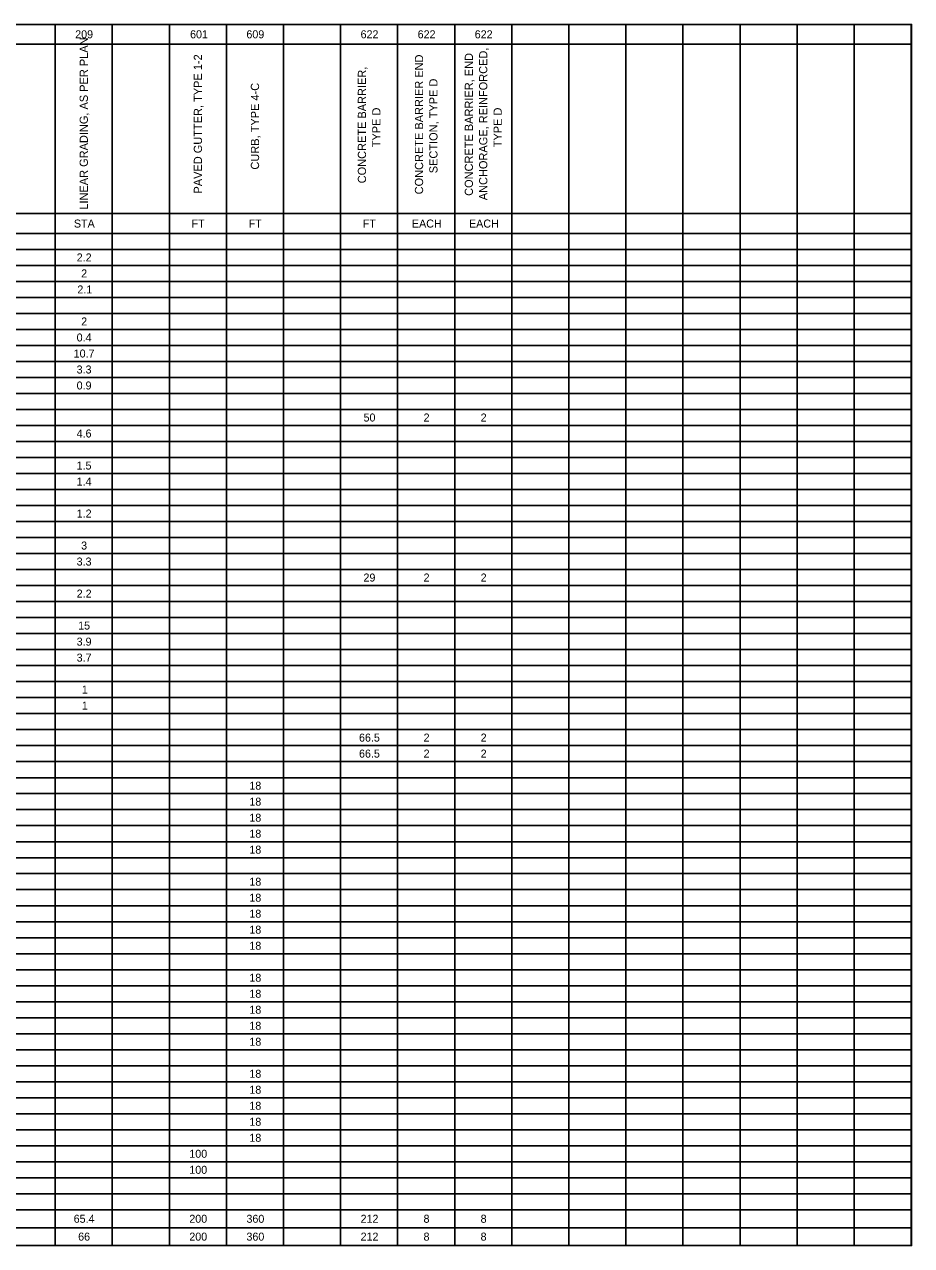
# Model space of a CAD drawing. Extents: x -542 to 295, y -281 to 32.
# Drawn here: x -1.11 to 14.14, y -130.59 to -109.59 of the extents above; entities that cross this region are included whole.
import ezdxf

# ---------------------------------------------------------------- set-up
doc = ezdxf.new("R2010")
doc.units = 0
doc.layers.add('SC_Scratch1', color=7, linetype='Continuous')
doc.layers.add('SH_Text', color=7, linetype='Continuous')

msp = doc.modelspace()

# ---------------------------------------------------------------- linework, layer by layer
at = {"layer": 'SC_Scratch1'}
msp.add_lwpolyline([(-16.359, -109.593), (14.141, -109.593), (14.141, -130.593), (-16.359, -130.593)], close=True, dxfattribs=at)
at = {"layer": 'SH_Text'}
for p, q in [((-16.359, -109.593), (14.136, -109.593)), ((-0.579, -109.593), (-0.579, -130.594)), ((0.402, -109.593), (0.402, -130.594)), ((1.383, -109.593), (1.383, -130.594)), ((2.364, -109.593), (2.364, -130.594)), ((3.345, -109.593), (3.345, -130.594)), ((4.326, -109.593), (4.326, -130.594)), ((5.307, -109.593), (5.307, -130.594)), ((6.288, -109.593), (6.288, -130.594)), ((7.269, -109.593), (7.269, -130.594)), ((8.25, -109.593), (8.25, -130.594)), ((9.231, -109.593), (9.231, -130.594)), ((10.212, -109.593), (10.212, -130.594)), ((11.193, -109.593), (11.193, -130.594)), ((12.174, -109.593), (12.174, -130.594)), ((13.155, -109.593), (13.155, -130.594)), ((14.136, -109.593), (14.136, -130.594)), ((-9.408, -109.933), (14.136, -109.933)), ((-9.408, -112.847), (14.136, -112.847)), ((-16.359, -113.187), (14.136, -113.187)), ((-16.359, -113.463), (14.136, -113.463)), ((-16.359, -113.738), (14.136, -113.738)), ((-16.359, -114.013), (14.136, -114.013)), ((-16.359, -114.288), (14.136, -114.288)), ((-16.359, -114.564), (14.136, -114.564)), ((-16.359, -114.839), (14.136, -114.839)), ((-16.359, -115.114), (14.136, -115.114)), ((-16.359, -115.389), (14.136, -115.389)), ((-16.359, -115.665), (14.136, -115.665)), ((-16.359, -115.94), (14.136, -115.94)), ((-16.359, -116.215), (14.136, -116.215)), ((-16.359, -116.491), (14.136, -116.491)), ((-16.359, -116.766), (14.136, -116.766)), ((-16.359, -117.041), (14.136, -117.041)), ((-16.359, -117.316), (14.136, -117.316)), ((-16.359, -117.592), (14.136, -117.592)), ((-16.359, -117.867), (14.136, -117.867)), ((-16.359, -118.142), (14.136, -118.142)), ((-16.359, -118.417), (14.136, -118.417)), ((-16.359, -118.693), (14.136, -118.693)), ((-16.359, -118.968), (14.136, -118.968)), ((-16.359, -119.243), (14.136, -119.243)), ((-16.359, -119.519), (14.136, -119.519)), ((-16.359, -119.794), (14.136, -119.794)), ((-16.359, -120.069), (14.136, -120.069)), ((-16.359, -120.344), (14.136, -120.344)), ((-16.359, -120.62), (14.136, -120.62)), ((-16.359, -120.895), (14.136, -120.895)), ((-16.359, -121.17), (14.136, -121.17)), ((-16.359, -121.445), (14.136, -121.445)), ((-16.359, -121.721), (14.136, -121.721)), ((-16.359, -121.996), (14.136, -121.996)), ((-16.359, -122.271), (14.136, -122.271)), ((-16.359, -122.547), (14.136, -122.547)), ((-16.359, -122.822), (14.136, -122.822)), ((-16.359, -123.097), (14.136, -123.097)), ((-16.359, -123.372), (14.136, -123.372)), ((-16.359, -123.648), (14.136, -123.648)), ((-16.359, -123.923), (14.136, -123.923)), ((-16.359, -124.198), (14.136, -124.198)), ((-16.359, -124.473), (14.136, -124.473)), ((-16.359, -124.749), (14.136, -124.749)), ((-16.359, -125.024), (14.136, -125.024)), ((-16.359, -125.299), (14.136, -125.299)), ((-16.359, -125.575), (14.136, -125.575)), ((-16.359, -125.85), (14.136, -125.85)), ((-16.359, -126.125), (14.136, -126.125)), ((-16.359, -126.4), (14.136, -126.4)), ((-16.359, -126.676), (14.136, -126.676)), ((-16.359, -126.951), (14.136, -126.951)), ((-16.359, -127.226), (14.136, -127.226)), ((-16.359, -127.501), (14.136, -127.501)), ((-16.359, -127.777), (14.136, -127.777)), ((-16.359, -128.052), (14.136, -128.052)), ((-16.359, -128.327), (14.136, -128.327)), ((-16.359, -128.603), (14.136, -128.603)), ((-16.359, -128.878), (14.136, -128.878)), ((-16.359, -129.153), (14.136, -129.153)), ((-16.359, -129.428), (14.136, -129.428)), ((-16.359, -129.704), (14.136, -129.704)), ((-16.359, -129.979), (14.136, -129.979)), ((-16.359, -130.287), (14.136, -130.287)), ((-16.359, -130.594), (14.136, -130.594))]:
    msp.add_line(p, q, dxfattribs=at)

# ---------------------------------------------------------------- texts
for s, height, p in [('209', 0.1376, (-0.236, -109.831)), ('601', 0.1376, (1.739, -109.831)), ('609', 0.1376, (2.707, -109.831)), ('622', 0.1376, (4.67, -109.831)), ('622', 0.1376, (5.651, -109.831)), ('622', 0.1376, (6.632, -109.831)), ('STA', 0.1376, (-0.258, -113.086)), ('FT', 0.1376, (1.765, -113.086)), ('FT', 0.1376, (2.746, -113.086)), ('FT', 0.1376, (4.708, -113.086)), ('EACH', 0.1376, (5.553, -113.086)), ('EACH', 0.1376, (6.534, -113.086)), ('2.2', 0.1376, (-0.21, -113.669)), ('2', 0.138, (-0.133, -113.944)), ('2.1', 0.1376, (-0.199, -114.22)), ('2', 0.138, (-0.133, -114.77)), ('0.4', 0.1376, (-0.211, -115.045)), ('10.7', 0.1376, (-0.262, -115.321)), ('3.3', 0.1376, (-0.211, -115.596)), ('0.9', 0.1376, (-0.211, -115.871)), ('50', 0.1376, (4.721, -116.422)), ('2', 0.138, (5.753, -116.422)), ('2', 0.138, (6.734, -116.422)), ('4.6', 0.1376, (-0.211, -116.697)), ('1.5', 0.1376, (-0.212, -117.248)), ('1.4', 0.1376, (-0.211, -117.523)), ('1.2', 0.1376, (-0.21, -118.073)), ('3', 0.138, (-0.134, -118.624)), ('3.3', 0.1376, (-0.211, -118.899)), ('29', 0.1376, (4.72, -119.174)), ('2', 0.138, (5.753, -119.174)), ('2', 0.138, (6.734, -119.174)), ('2.2', 0.1376, (-0.21, -119.45)), ('15', 0.1376, (-0.185, -120)), ('3.9', 0.1376, (-0.211, -120.276)), ('3.7', 0.1376, (-0.211, -120.551)), ('1', 0.138, (-0.122, -121.101)), ('1', 0.138, (-0.122, -121.377)), ('66.5', 0.1376, (4.643, -121.927)), ('2', 0.138, (5.753, -121.927)), ('2', 0.138, (6.734, -121.927)), ('66.5', 0.1376, (4.643, -122.202)), ('2', 0.138, (5.753, -122.202)), ('2', 0.138, (6.734, -122.202)), ('18', 0.1376, (2.758, -122.753)), ('18', 0.1376, (2.758, -123.028)), ('18', 0.1376, (2.758, -123.304)), ('18', 0.1376, (2.758, -123.579)), ('18', 0.1376, (2.758, -123.854)), ('18', 0.1376, (2.758, -124.405)), ('18', 0.1376, (2.758, -124.68)), ('18', 0.1376, (2.758, -124.955)), ('18', 0.1376, (2.758, -125.23)), ('18', 0.1376, (2.758, -125.506)), ('18', 0.1376, (2.758, -126.056)), ('18', 0.1376, (2.758, -126.332)), ('18', 0.1376, (2.758, -126.607)), ('18', 0.1376, (2.758, -126.882)), ('18', 0.1376, (2.758, -127.157)), ('18', 0.1376, (2.758, -127.708)), ('18', 0.1376, (2.758, -127.983)), ('18', 0.1376, (2.758, -128.258)), ('18', 0.1376, (2.758, -128.534)), ('18', 0.1376, (2.758, -128.809)), ('100', 0.1376, (1.726, -129.084)), ('100', 0.1376, (1.726, -129.36)), ('65.4', 0.1376, (-0.262, -130.202)), ('200', 0.1376, (1.726, -130.202)), ('360', 0.1376, (2.708, -130.202)), ('212', 0.1376, (4.67, -130.202)), ('8', 0.138, (5.752, -130.202)), ('8', 0.138, (6.733, -130.202)), ('66', 0.1376, (-0.185, -130.509)), ('200', 0.1376, (1.726, -130.509)), ('360', 0.1376, (2.708, -130.509)), ('212', 0.1376, (4.67, -130.509)), ('8', 0.138, (5.752, -130.509)), ('8', 0.138, (6.733, -130.509))]:
    msp.add_text(s, height=height, dxfattribs=at).set_placement(p)
for s, height, p in [('LINEAR GRADING, AS PER PLAN', 0.14133, (-0.018, -112.778)), ('ANCHORAGE, REINFORCED, ', 0.14133, (6.849, -112.616)), ('PAVED GUTTER, TYPE 1-2', 0.14133, (1.944, -112.501)), ('CONCRETE BARRIER END ', 0.14133, (5.745, -112.515)), ('CONCRETE BARRIER, END ', 0.14133, (6.602, -112.541)), ('CONCRETE BARRIER, ', 0.14133, (4.764, -112.325)), ('CURB, TYPE 4-C', 0.14133, (2.925, -112.089)), ('SECTION, TYPE D', 0.14133, (5.992, -112.152)), ('TYPE D', 0.1413, (5.011, -111.705)), ('TYPE D', 0.1413, (7.097, -111.705))]:
    msp.add_text(s, height=height, rotation=90, dxfattribs=at).set_placement(p)

doc.saveas('drawing.dxf')
